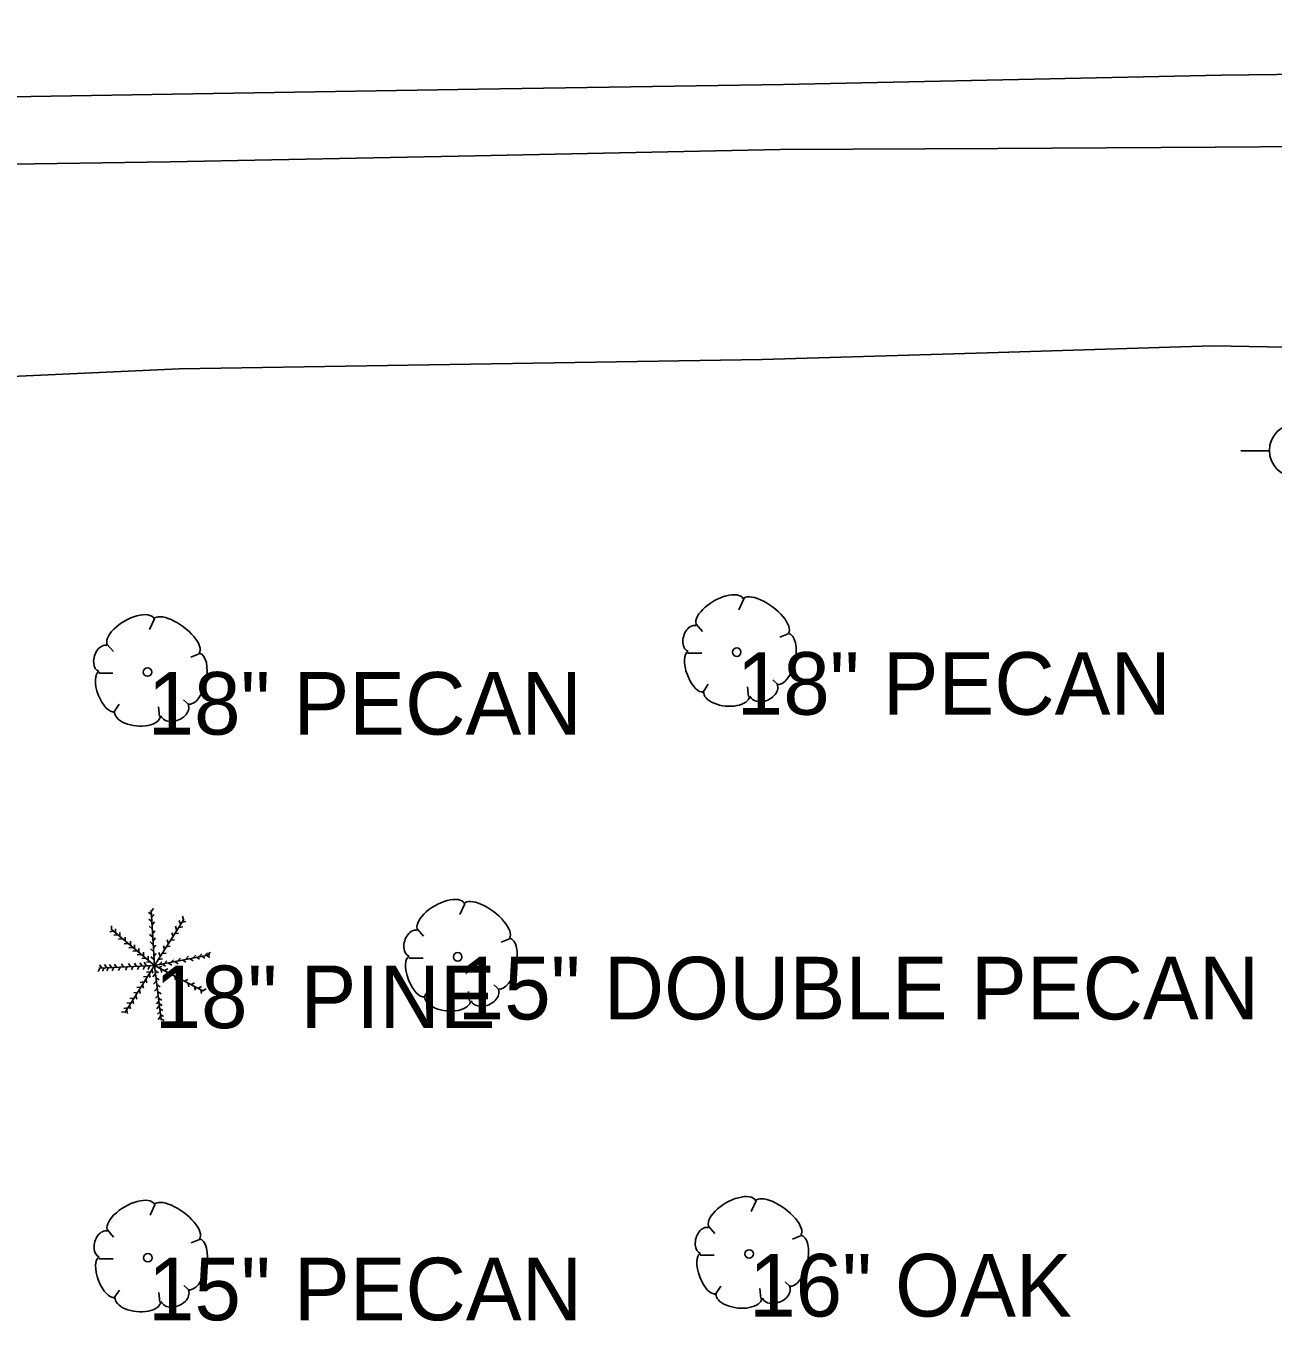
# Model space of a CAD drawing. Extents: x 1800653 to 1804042, y 522635 to 523313.
# Drawn here: x 1802796.8 to 1802896.5, y 522883.4 to 522987 of the extents above; entities that cross this region are included whole.
import ezdxf

# ---------------------------------------------------------------- set-up
doc = ezdxf.new("R2010")
doc.units = 0
for name, color, linetype in [('S_DITCHLINE', 7, 'Continuous'), ('S_EDGE_PAVEMENT', 7, 'Continuous'), ('S_SHOULDER', 7, 'Continuous'), ('S_TREE', 7, 'Continuous'), ('S_TREE_ANNOT', 7, 'Continuous'), ('S_UTILITY_POLE', 7, 'Continuous')]:
    doc.layers.add(name, color=color, linetype=linetype)

msp = doc.modelspace()

# ---------------------------------------------------------------- linework, layer by layer
at = {"layer": 'S_DITCHLINE'}
msp.add_lwpolyline([(1802794.52, 522958.95), (1802809.08, 522959.6), (1802832.38, 522959.97), (1802855.67, 522960.34), (1802873.68, 522960.89), (1802891.69, 522961.44), (1802913.57, 522961.04), (1802935.44, 522960.63), (1802936.18, 522941.07), (1802936.91, 522921.5), (1802937.57, 522902.46), (1802938.23, 522883.42)], dxfattribs=at)
at = {"layer": 'S_EDGE_PAVEMENT'}
msp.add_lwpolyline([(1802793.98, 522981.33), (1802808.56, 522981.56), (1802832.98, 522981.95), (1802857.39, 522982.34), (1802874.9, 522982.71), (1802892.4, 522983.08), (1802910.08, 522983.28), (1802927.76, 522983.47), (1802945.52, 522983.73), (1802963.29, 522983.99), (1802980.26, 522984.41), (1802997.22, 522984.84), (1803010.53, 522984.99), (1803023.83, 522985.13), (1803037.14, 522985.28), (1803050.45, 522985.42), (1803063.93, 522985.65), (1803077.42, 522985.88), (1803090.9, 522986.1), (1803104.39, 522986.33), (1803117.62, 522986.56), (1803130.85, 522986.79), (1803144.08, 522987.01)], dxfattribs=at)
at = {"layer": 'S_SHOULDER'}
msp.add_lwpolyline([(1802793.86, 522975.94), (1802808.36, 522976.14), (1802832.74, 522976.63), (1802857.12, 522977.13), (1802874.52, 522977.23), (1802891.91, 522977.33), (1802909.78, 522977.47), (1802927.64, 522977.61), (1802945.31, 522977.97), (1802962.99, 522978.33), (1802984.7, 522978.6), (1803006.42, 522978.88), (1803028.14, 522979.15), (1803049.85, 522979.42), (1803063.55, 522979.76), (1803077.25, 522980.09), (1803090.95, 522980.43), (1803104.65, 522980.76), (1803117.85, 522980.81), (1803131.05, 522980.86), (1803144.24, 522980.9)], dxfattribs=at)
at = {"layer": 'S_TREE'}
for p, q in [((1802854.2, 522941.21), (1802853.81, 522940.35)), ((1802807.11, 522939.62), (1802806.72, 522938.77)), ((1802850.4, 522939.19), (1802850.9, 522938.61)), ((1802857.76, 522938.42), (1802857.1, 522938.15)), ((1802803.31, 522937.6), (1802803.82, 522937.02)), ((1802810.68, 522936.83), (1802810.02, 522936.56)), ((1802849.74, 522936.87), (1802850.86, 522936.87)), ((1802802.66, 522935.28), (1802803.78, 522935.28)), ((1802856.99, 522934.31), (1802856.52, 522934.74)), ((1802850.9, 522933.69), (1802851.37, 522934.39)), ((1802854.58, 522933.42), (1802854.51, 522934.19)), ((1802803.82, 522932.1), (1802804.28, 522932.8)), ((1802807.5, 522931.83), (1802807.42, 522932.6)), ((1802809.9, 522932.72), (1802809.44, 522933.15)), ((1802806.85, 522915.99), (1802806.63, 522916.19)), ((1802807.11, 522911.91), (1802806.84, 522916.35)), ((1802806.85, 522916.24), (1802807.04, 522916.48)), ((1802806.88, 522915.76), (1802807.07, 522916)), ((1802831.9, 522916.85), (1802831.51, 522916)), ((1802803.68, 522914.8), (1802803.68, 522915.1)), ((1802806.89, 522915.43), (1802806.66, 522915.63)), ((1802806.91, 522914.86), (1802806.69, 522915.06)), ((1802806.91, 522915.16), (1802807.1, 522915.4)), ((1802807.11, 522911.91), (1802809.45, 522915.6)), ((1802808.88, 522914.77), (1802808.79, 522915.06)), ((1802809.07, 522914.96), (1802809.37, 522915)), ((1802809.18, 522915.22), (1802809.09, 522915.51)), ((1802809.31, 522915.39), (1802809.61, 522915.43)), ((1802809.42, 522915.57), (1802809.34, 522915.85)), ((1802803.82, 522914.66), (1802803.53, 522914.62)), ((1802807.11, 522911.91), (1802803.64, 522914.82)), ((1802804.17, 522914.38), (1802803.87, 522914.35)), ((1802804, 522914.55), (1802804, 522914.85)), ((1802804.53, 522914.06), (1802804.24, 522914.03)), ((1802804.35, 522914.26), (1802804.35, 522914.56)), ((1802804.77, 522913.89), (1802804.77, 522914.19)), ((1802805.18, 522913.57), (1802805.18, 522913.87)), ((1802806.94, 522914.2), (1802806.72, 522914.4)), ((1802806.95, 522914.45), (1802807.14, 522914.69)), ((1802807.01, 522913.89), (1802807.2, 522914.12)), ((1802808.21, 522913.69), (1802808.12, 522913.97)), ((1802808.42, 522913.93), (1802808.72, 522913.97)), ((1802808.59, 522914.26), (1802808.5, 522914.54)), ((1802808.75, 522914.47), (1802809.04, 522914.51)), ((1802828.1, 522914.84), (1802828.61, 522914.26)), ((1802835.47, 522914.06), (1802834.81, 522913.79)), ((1802804.99, 522913.68), (1802804.69, 522913.66)), ((1802805.35, 522913.35), (1802805.05, 522913.33)), ((1802805.69, 522913.09), (1802805.39, 522913.06)), ((1802805.5, 522913.28), (1802805.5, 522913.58)), ((1802805.87, 522912.98), (1802805.87, 522913.28)), ((1802806.24, 522912.68), (1802806.24, 522912.98)), ((1802806.98, 522913.6), (1802806.75, 522913.8)), ((1802807.02, 522913.04), (1802806.79, 522913.24)), ((1802807.03, 522913.32), (1802807.22, 522913.55)), ((1802807.05, 522912.65), (1802807.24, 522912.88)), ((1802807.55, 522912.67), (1802807.46, 522912.96)), ((1802807.74, 522912.87), (1802808.04, 522912.91)), ((1802807.91, 522913.2), (1802807.83, 522913.48)), ((1802808.08, 522913.41), (1802808.37, 522913.46)), ((1802810.69, 522912.63), (1802810.89, 522912.85)), ((1802811.14, 522912.72), (1802811.34, 522912.94)), ((1802811.36, 522912.77), (1802811.56, 522912.99)), ((1802807.11, 522911.91), (1802802.66, 522911.7)), ((1802802.89, 522911.73), (1802802.72, 522911.97)), ((1802803.28, 522911.75), (1802803.11, 522912)), ((1802803.68, 522911.75), (1802803.51, 522912)), ((1802804.08, 522911.78), (1802803.91, 522912.02)), ((1802804.36, 522911.79), (1802804.23, 522911.52)), ((1802804.64, 522911.79), (1802804.48, 522912.04)), ((1802807.11, 522911.91), (1802804.73, 522908.14)), ((1802804.92, 522911.81), (1802804.79, 522911.54)), ((1802805.2, 522911.83), (1802805.03, 522912.08)), ((1802805.41, 522911.83), (1802805.27, 522911.56)), ((1802805.68, 522911.84), (1802805.51, 522912.09)), ((1802806.03, 522912.79), (1802805.73, 522912.77)), ((1802805.88, 522911.86), (1802805.74, 522911.59)), ((1802806.12, 522911.88), (1802805.95, 522912.13)), ((1802806.4, 522912.49), (1802806.1, 522912.47)), ((1802806.33, 522911.86), (1802806.2, 522911.59)), ((1802806.45, 522911.92), (1802806.28, 522912.17)), ((1802806.76, 522912.2), (1802806.46, 522912.17)), ((1802806.59, 522912.36), (1802806.59, 522912.66)), ((1802806.72, 522911.88), (1802806.59, 522911.61)), ((1802807.03, 522912.42), (1802806.81, 522912.62)), ((1802807.11, 522911.91), (1802811.53, 522912.78)), ((1802807.11, 522911.91), (1802811.02, 522909.87)), ((1802807.11, 522911.91), (1802807.64, 522907.54)), ((1802807.44, 522911.73), (1802807.7, 522911.87)), ((1802807.46, 522912.4), (1802807.75, 522912.45)), ((1802807.48, 522912), (1802807.69, 522912.22)), ((1802807.73, 522912.03), (1802807.98, 522911.87)), ((1802807.88, 522912.06), (1802808.09, 522912.28)), ((1802808.24, 522912.11), (1802808.5, 522911.95)), ((1802808.41, 522912.16), (1802808.62, 522912.38)), ((1802808.76, 522912.22), (1802809.01, 522912.06)), ((1802808.98, 522912.29), (1802809.18, 522912.51)), ((1802809.37, 522912.35), (1802809.62, 522912.19)), ((1802809.61, 522912.43), (1802809.82, 522912.65)), ((1802809.95, 522912.46), (1802810.2, 522912.3)), ((1802810.21, 522912.52), (1802810.41, 522912.74)), ((1802810.46, 522912.57), (1802810.71, 522912.41)), ((1802810.88, 522912.66), (1802811.14, 522912.5)), ((1802811.29, 522912.72), (1802811.54, 522912.56)), ((1802827.45, 522912.51), (1802828.57, 522912.51)), ((1802802.74, 522911.7), (1802802.61, 522911.43)), ((1802803.09, 522911.73), (1802802.95, 522911.46)), ((1802803.43, 522911.75), (1802803.3, 522911.48)), ((1802803.85, 522911.76), (1802803.72, 522911.49)), ((1802806.54, 522911.05), (1802806.24, 522911.02)), ((1802806.41, 522910.82), (1802806.49, 522910.53)), ((1802806.78, 522911.42), (1802806.48, 522911.38)), ((1802806.69, 522911.26), (1802806.76, 522910.97)), ((1802806.9, 522911.59), (1802806.98, 522911.3)), ((1802807.17, 522911.24), (1802806.97, 522911.01)), ((1802807.19, 522911.49), (1802807.44, 522911.33)), ((1802807.22, 522910.93), (1802807.48, 522910.78)), ((1802807.62, 522911.64), (1802807.69, 522911.35)), ((1802807.91, 522911.51), (1802808.18, 522911.65)), ((1802808.2, 522911.33), (1802808.27, 522911.04)), ((1802808.47, 522911.2), (1802808.73, 522911.34)), ((1802808.73, 522911.06), (1802808.8, 522910.76)), ((1802809.02, 522910.92), (1802809.29, 522911.06)), ((1802809.26, 522910.79), (1802809.33, 522910.49)), ((1802809.51, 522910.66), (1802809.77, 522910.8)), ((1802805.75, 522909.77), (1802805.45, 522909.73)), ((1802806.01, 522910.19), (1802805.71, 522910.15)), ((1802805.9, 522909.98), (1802805.97, 522909.69)), ((1802806.26, 522910.6), (1802805.97, 522910.57)), ((1802806.15, 522910.4), (1802806.23, 522910.11)), ((1802807.23, 522910.66), (1802807.04, 522910.43)), ((1802807.32, 522910.1), (1802807.12, 522909.87)), ((1802807.31, 522910.37), (1802807.56, 522910.21)), ((1802807.37, 522909.82), (1802807.63, 522909.66)), ((1802809.79, 522910.49), (1802809.86, 522910.2)), ((1802810.04, 522910.39), (1802810.31, 522910.53)), ((1802810.31, 522910.23), (1802810.38, 522909.94)), ((1802810.59, 522910.11), (1802810.86, 522910.25)), ((1802810.8, 522909.98), (1802810.87, 522909.69)), ((1802810.99, 522909.91), (1802811.25, 522910.05)), ((1802828.61, 522909.34), (1802829.07, 522910.03)), ((1802832.29, 522909.06), (1802832.21, 522909.84)), ((1802834.69, 522909.96), (1802834.23, 522910.38)), ((1802805.21, 522908.94), (1802804.91, 522908.91)), ((1802805.11, 522908.73), (1802805.18, 522908.44)), ((1802805.45, 522909.31), (1802805.15, 522909.28)), ((1802805.37, 522909.13), (1802805.44, 522908.84)), ((1802805.61, 522909.51), (1802805.69, 522909.22)), ((1802807.39, 522909.53), (1802807.19, 522909.3)), ((1802807.45, 522909.07), (1802807.26, 522908.84)), ((1802807.49, 522908.69), (1802807.3, 522908.46)), ((1802807.44, 522909.31), (1802807.7, 522909.15)), ((1802807.48, 522908.88), (1802807.73, 522908.72)), ((1802804.76, 522908.22), (1802804.46, 522908.19)), ((1802804.96, 522908.53), (1802804.66, 522908.49)), ((1802804.88, 522908.39), (1802804.96, 522908.09)), ((1802807.55, 522908.24), (1802807.35, 522908.02)), ((1802807.6, 522907.83), (1802807.4, 522907.6)), ((1802807.52, 522908.47), (1802807.78, 522908.31)), ((1802807.59, 522908), (1802807.84, 522907.85)), ((1802807.62, 522907.66), (1802807.88, 522907.51)), ((1802807.14, 522892.8), (1802806.75, 522891.95)), ((1802855.19, 522893.1), (1802854.8, 522892.25)), ((1802851.39, 522891.09), (1802851.89, 522890.5)), ((1802803.34, 522890.79), (1802803.84, 522890.21)), ((1802810.7, 522890.01), (1802810.04, 522889.74)), ((1802858.75, 522890.31), (1802858.09, 522890.04)), ((1802802.68, 522888.46), (1802803.81, 522888.46)), ((1802850.73, 522888.76), (1802851.85, 522888.76)), ((1802803.84, 522885.29), (1802804.31, 522885.98)), ((1802809.93, 522885.91), (1802809.46, 522886.33)), ((1802851.89, 522885.58), (1802852.36, 522886.28)), ((1802855.57, 522885.31), (1802855.5, 522886.09)), ((1802857.98, 522886.2), (1802857.51, 522886.63)), ((1802807.53, 522885.02), (1802807.45, 522885.79))]:
    msp.add_line(p, q, dxfattribs=at)
for centre in [(1802853.64, 522936.96), (1802806.55, 522935.37), (1802831.34, 522912.61), (1802854.63, 522888.86), (1802806.58, 522888.56)]:
    msp.add_circle(centre, 0.341, dxfattribs=at)
for centre, major_axis, ratio, start_param, end_param in [((1802852.3, 522940.16), (1.86, 1.08), 0.471018, 0, 3.141593), ((1802855.96, 522939.84), (-1.81, 1.36), 0.405113, 3.141593, 6.283186), ((1802805.22, 522938.57), (1.86, 1.08), 0.471018, 0, 3.141593), ((1802808.87, 522938.25), (-1.81, 1.36), 0.405113, 3.141593, 6.283186), ((1802850.07, 522938.05), (0.31, 1.03), 0.646762, 0, 3.141593), ((1802857.31, 522936.43), (0.46, 2.04), 0.482994, 3.141593, 6.283185), ((1802802.98, 522936.46), (0.31, 1.03), 0.646762, 0, 3.141593), ((1802810.23, 522934.84), (0.46, 2.04), 0.482994, 3.141593, 6.283185), ((1802850.37, 522935.4), (-0.61, 1.6), 0.420543, 6.283185, 9.424777), ((1802803.29, 522933.81), (-0.61, 1.6), 0.420543, 6.283185, 9.424777), ((1802852.83, 522933.62), (-1.83, 0.19), 0.529943, 0, 3.141593), ((1802855.79, 522933.91), (1.09, 0.46), 0.711534, 3.141592, 6.283185), ((1802808.71, 522932.32), (1.09, 0.46), 0.711534, 3.141592, 6.283185), ((1802805.75, 522932.03), (-1.83, 0.19), 0.529943, 0, 3.141593), ((1802830.01, 522915.81), (1.86, 1.08), 0.471018, 0, 3.141593), ((1802833.66, 522915.49), (-1.81, 1.36), 0.405113, 3.141593, 6.283186), ((1802827.77, 522913.69), (0.31, 1.03), 0.646762, 0, 3.141593), ((1802835.02, 522912.08), (0.46, 2.04), 0.482994, 3.141593, 6.283185), ((1802828.08, 522911.04), (-0.61, 1.6), 0.420543, 6.283185, 9.424777), ((1802833.5, 522909.56), (1.09, 0.46), 0.711534, 3.141592, 6.283185), ((1802830.54, 522909.26), (-1.83, 0.19), 0.529943, 0, 3.141593), ((1802805.24, 522891.76), (1.86, 1.08), 0.471018, 0, 3.141593), ((1802808.9, 522891.44), (-1.81, 1.36), 0.405113, 3.141593, 6.283186), ((1802853.29, 522892.06), (1.86, 1.08), 0.471018, 0, 3.141593), ((1802856.95, 522891.73), (-1.81, 1.36), 0.405113, 3.141593, 6.283186), ((1802803.01, 522889.65), (0.31, 1.03), 0.646762, 0, 3.141593), ((1802810.25, 522888.03), (0.46, 2.04), 0.482994, 3.141593, 6.283185), ((1802851.06, 522889.94), (0.31, 1.03), 0.646762, 0, 3.141593), ((1802858.3, 522888.33), (0.46, 2.04), 0.482994, 3.141593, 6.283185), ((1802803.31, 522887), (-0.61, 1.6), 0.420543, 6.283185, 9.424777), ((1802851.36, 522887.29), (-0.61, 1.6), 0.420543, 6.283185, 9.424777), ((1802808.73, 522885.51), (1.09, 0.46), 0.711534, 3.141592, 6.283185), ((1802856.78, 522885.8), (1.09, 0.46), 0.711534, 3.141592, 6.283185), ((1802805.78, 522885.22), (-1.83, 0.19), 0.529943, 0, 3.141593), ((1802853.82, 522885.51), (-1.83, 0.19), 0.529943, 0, 3.141593)]:
    msp.add_ellipse(centre, major_axis=major_axis, ratio=ratio, start_param=start_param, end_param=end_param, dxfattribs=at)
at = {"layer": 'S_UTILITY_POLE'}
msp.add_line((1802896.25, 522953.06), (1802893.93, 522953.06), dxfattribs=at)
msp.add_circle((1802898.35, 522953.08), 2.13, dxfattribs=at)

# ---------------------------------------------------------------- texts
at = {"layer": 'S_TREE_ANNOT'}
for s, p in [('18" PECAN', (1802853.64, 522931.96)), ('18" PECAN', (1802806.55, 522930.37)), ('18" PINE', (1802807.11, 522906.91)), ('15" DOUBLE PECAN', (1802831.34, 522907.61)), ('15" PECAN', (1802806.58, 522883.56)), ('16" OAK', (1802854.63, 522883.86))]:
    msp.add_text(s, height=5, dxfattribs=at).set_placement(p)

doc.saveas('drawing.dxf')
